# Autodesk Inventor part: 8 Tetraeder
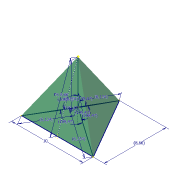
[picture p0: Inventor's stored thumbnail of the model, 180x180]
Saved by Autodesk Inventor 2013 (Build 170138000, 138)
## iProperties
Created: 2012-10
Part Number: 8 Tetraeder
Material: Allgemein
Vendor: www.inventor-faq.de
Document SubType Name: Modeling
Designer: Administrator
Manufacturer: www.inventor-faq.de
Density: 1 g/cm^3
Mass: 0.117851 g
Surface Area: 1.73205 cm^2
Volume: 0.117851 cm^3
RuleStatus: InUse
AfterDocOpen0: inventorfaq
BeforeDocSave0: inventorfaq
Author: Administrator
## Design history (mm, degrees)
sketch "Skizze1"
  geometry: L1 (0, 5.774)-(5, -2.887); L2 (5, -2.887)-(-5, -2.887); L3 (-5, -2.887)-(0, 5.774); 2 further points
  constraints: 6 end point, 1 coincident, 1 horizontal, 7 other
  dimensions: "d0" = 10 distance of L1.end L2.end; "d1" = 8.66025 distance from line of L1.start L2 (derived)
sketch "Skizze2"
  geometry: L1 (0, 0)-(0, 8.165); L2 (-2.887, 0)-(0, 8.165)
  constraints: 4 end point, 1 vertical
  dimensions: "d7" = 8.66025 distance of L2.start L1.end (= d1)
workpoint "Arbeitspunkt2"
feature "Erhebung2" dims "d8" = 0, "d9" = 90 deg, "d10" = 0, "d11" = 90 deg
node "Schwerpunkt FIX"
sketch "3D-Skizze2" dims "d12" = 6.124 (derived), "d13" = 6.124 (derived), "d14" = 6.124 (derived), "d15" = 6.124 (derived), "d16" = 19.10612 (derived), "d17" = 19.10612 (derived), "d18" = 19.10612 (derived), "d19" = 19.10612 (derived), "d20" = 19.10612 (derived), "d21" = 19.10612 (derived)
node "Volumenkörper2"
